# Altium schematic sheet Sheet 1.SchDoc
size 431 x 279 mm
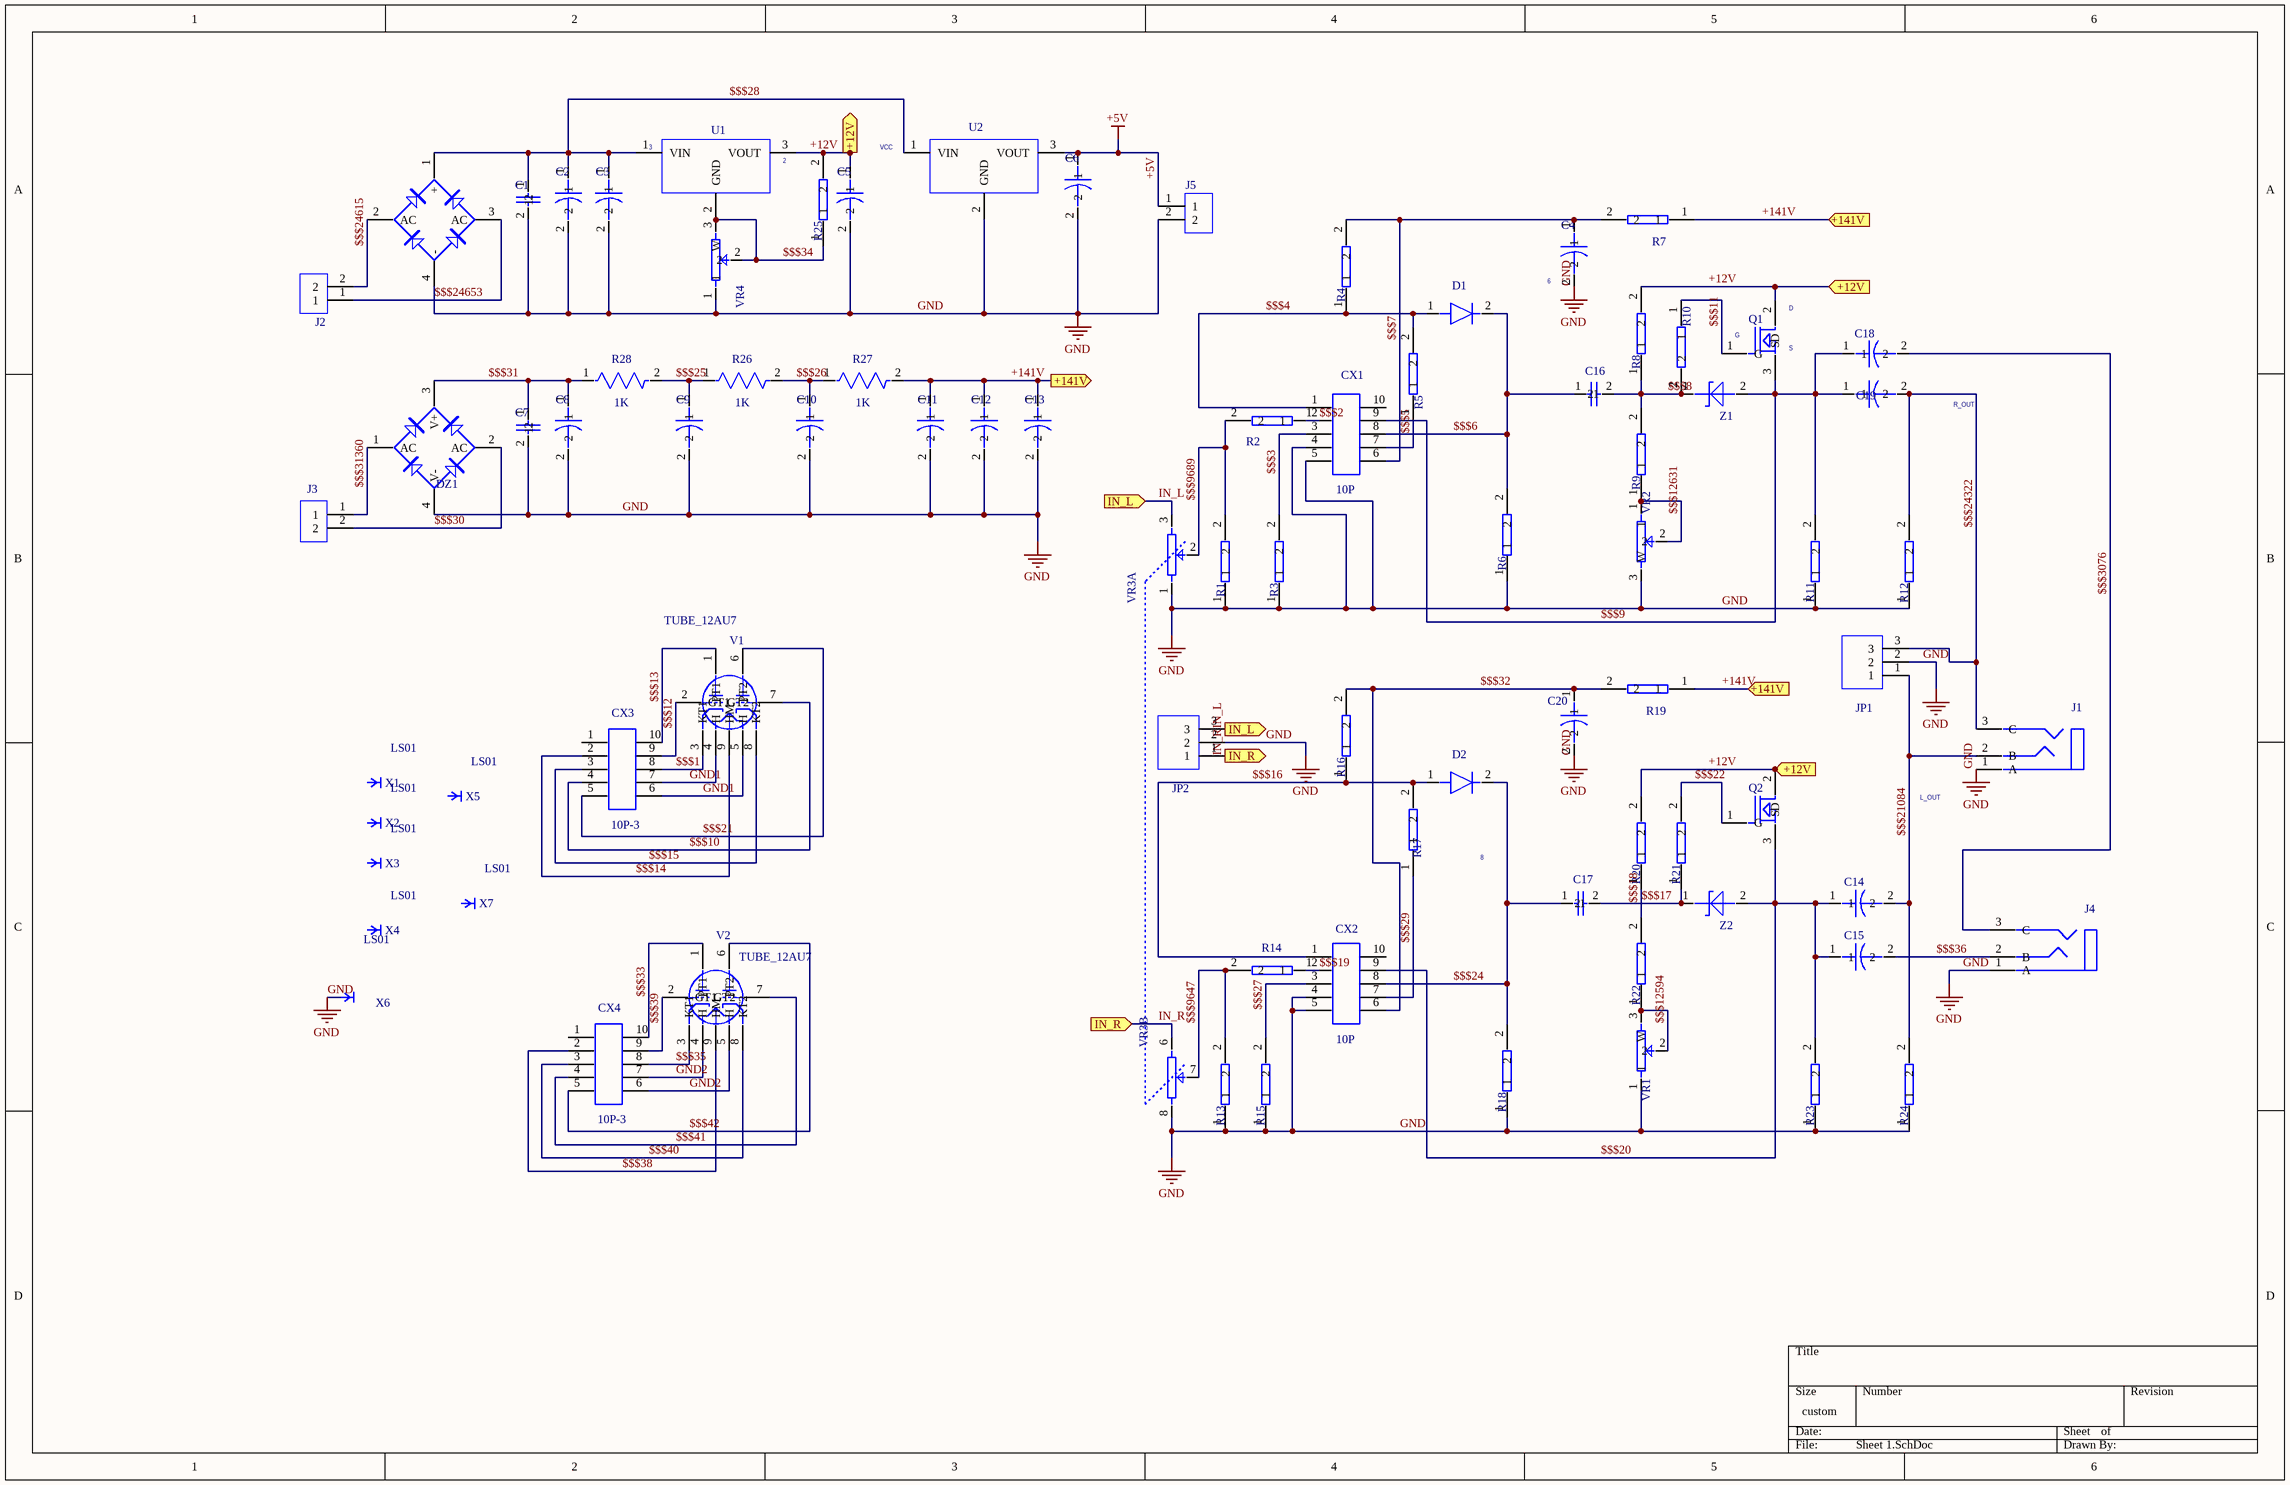
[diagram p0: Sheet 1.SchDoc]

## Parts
C1  CAP  (value not drawn)
C2  CAPACITOR_POL  (value not drawn)
C3  CAPACITOR_POL  (value not drawn)
C4  CAPACITOR_POL  (value not drawn)
C5  CAPACITOR_POL  (value not drawn)
C6  CAPACITOR_POL  (value not drawn)
C7  CAP  (value not drawn)
C8  CAPACITOR_POL  (value not drawn)
C9  CAPACITOR_POL  (value not drawn)
C10  CAPACITOR_POL  (value not drawn)
C11  CAPACITOR_POL  (value not drawn)
C12  CAPACITOR_POL  (value not drawn)
C13  CAPACITOR_POL  (value not drawn)
C14  CAP-5  (value not drawn)
C15  CAP-5  (value not drawn)
C16  CAP  (value not drawn)
C17  CAP  (value not drawn)
C18  CAP-5  (value not drawn)
C19  CAP-5  (value not drawn)
C20  CAPACITOR_POL  (value not drawn)
CX1  10P
CX2  10P
CX3  10P-3
CX4  10P-3
D1  FR107  (value not drawn)
D2  FR107  (value not drawn)
D3  KBL-5.0  (value not drawn)
DZ1  BRIDGE2  (value not drawn)
J1  M6.5  (value not drawn)
J2  CON2  (value not drawn)
J3  CON2  (value not drawn)
J4  M6.5  (value not drawn)
J5  CON2  (value not drawn)
JP1  HEADER_3  (value not drawn)
JP2  HEADER_3  (value not drawn)
Q1  IRF640  (value not drawn)
Q2  IRF640  (value not drawn)
R1  RES2  (value not drawn)
R2  RES2  (value not drawn)
R3  RES2  (value not drawn)
R4  RES2  (value not drawn)
R5  RES2  (value not drawn)
R6  RES2  (value not drawn)
R7  RES2  (value not drawn)
R8  RES2  (value not drawn)
R9  RES2  (value not drawn)
R10  RES2  (value not drawn)
R11  RES2  (value not drawn)
R12  RES2  (value not drawn)
R13  RES2  (value not drawn)
R14  RES2  (value not drawn)
R15  RES2  (value not drawn)
R16  RES2  (value not drawn)
R17  RES2  (value not drawn)
R18  RES2  (value not drawn)
R19  RES2  (value not drawn)
R20  RES2  (value not drawn)
R21  RES2  (value not drawn)
R22  RES2  (value not drawn)
R23  RES2  (value not drawn)
R24  RES2  (value not drawn)
R25  RES2  (value not drawn)
R26  value 1K  (hidden comment: RES-1W)
R27  value 1K  (hidden comment: RES-1W)
R28  value 1K  (hidden comment: RES-1W)
U1  VOLTREG  (value not drawn)
U2  VOLTREG  (value not drawn)
V1  TUBE_12AU7
V2  TUBE_12AU7
VR1  RP-3296  (value not drawn)
VR2  RP-3296  (value not drawn)
VR3  VR-27  (value not drawn)  (parts A,B of 2)
VR4  RP-3296  (value not drawn)
X1  LS01
X2  LS01
X3  LS01
X4  LS01
X5  LS01
X6  LS01
X7  LS01
Z1  ZENER2  (value not drawn)
Z2  ZENER2  (value not drawn)

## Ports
+12V, +141V, IN_L, IN_R

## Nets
$$$24653: C1.2 C2.2 C3.2 C4.2 C5.2 C6.2 C7.2 C8.2 C9.2 C10.2 C11.2 C12.2 C13.2 C20.2 CX1.4 CX1.5 CX2.4 CX2.5 D3.3(AC) D3.4(-) DZ1.4(V-) J1.1(A) J2.1 J4.1(A) J5.2 JP1.2 JP2.2 R1.1 R3.1 R6.1 R11.1 R12.1 R13.1 R15.1 R18.1 R23.1 R24.1 U2.2(GND) VR1.1 VR2.3(W) VR3.1 VR3.8 VR4.1  [also labelled GND]
+5V: C6.1 J5.1 U2.3(VOUT)
$$$1: CX3.8 V1.3(KT1)
$$$2: CX1.2 R2.1
$$$3: CX1.3 R3.2
$$$4: CX1.1 D1.1 R4.1 R5.2
$$$5: C16.1 C18.1 C19.1 CX1.7 CX1.8 CX1.9 D1.2 Q1.3(S) R5.1 R6.2 R11.2 Z1.2  [also labelled $$$6, $$$9]
$$$7: C4.1 CX1.6 R4.2 R7.2
$$$8: C16.2 R8.1 R9.2 R10.2 Z1.1
$$$10: CX3.4 V1.7(GT2)
$$$11: Q1.1(G) R10.1
$$$12: CX3.9 V1.2(GT1)
$$$13: CX3.10 V1.1(PT1)
$$$14: CX3.2 V1.9(HM)
$$$15: CX3.3 V1.8(KT2)
$$$16: CX2.1 D2.1 R16.1 R17.2
$$$17: C17.2 R20.1 R21.1 R22.2 Z2.1  [also labelled $$$18]
$$$19: CX2.2 R14.1
$$$20: C14.1 C15.1 CX2.9 Q2.3(S) R23.2 Z2.2
$$$21: CX3.5 V1.6(PT2)
$$$22: Q2.1(G) R21.2
$$$24: C17.1 CX2.8 D2.2 R18.2
$$$25: C9.1 R26.1 R28.2
$$$26: C10.1 R26.2 R27.1
$$$27: CX2.3 R15.2
$$$28: C1.1 C2.1 C3.1 D3.1(+) U1.1(VIN) U2.1(VIN)
$$$29: CX2.7 R17.1
$$$30: DZ1.2(AC) J3.2
$$$31: C7.1 C8.1 DZ1.3(V+) R28.1
$$$32: C20.1 CX2.6 R16.2 R19.2
$$$33: CX4.10 V2.1(PT1)
$$$34: R25.1 U1.2(GND) VR4.2 VR4.3(W)
$$$35: CX4.8 V2.3(KT1)
$$$36: C15.2 J4.2(B)
$$$38: CX4.2 V2.9(HM)
$$$39: CX4.9 V2.2(GT1)
$$$40: CX4.3 V2.8(KT2)
$$$41: CX4.4 V2.7(GT2)
$$$42: CX4.5 V2.6(PT2)
$$$3076: C18.2 J4.3(C)
$$$9647: R13.2 R14.2 VR3.7
$$$9689: R1.2 R2.2 VR3.2
$$$12594: R22.1 VR1.2 VR1.3(W)
$$$12631: R9.1 VR2.1 VR2.2
$$$21084: C14.2 J1.2(B) JP1.1 R24.2
$$$24322: C19.2 J1.3(C) JP1.3 R12.2
$$$24615: D3.2(AC) J2.2
$$$31360: DZ1.1(AC) J3.1
+12V: C5.1 Q1.2(D) Q2.2(D) R8.2 R20.2 R25.2 U1.3(VOUT) ; port +12V
+141V: C11.1 C12.1 C13.1 R7.1 R19.1 R27.2 ; port +141V
GND1: CX3.6 CX3.7 V1.4(H) V1.5(H)
GND2: CX4.6 CX4.7 V2.4(H) V2.5(H)
IN_L: JP2.3 VR3.3 ; port IN_L
IN_R: JP2.1 VR3.6 ; port IN_R

Not connected (* = marked no-connect by the designer): CX1 10; CX2 10; CX3 1; CX4 1

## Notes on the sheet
- (near U1) 3
- (near U1) 2
- VCC
- (near C4) 6
- (near Q1) G
- (near Q1) D
- (near Q1) S
- R_OUT
- L_OUT
- 8

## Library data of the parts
C1 C7 = CAP: Capacitor; Value: ???; PCB DECAL: CAP-300MIL
C2-C6 C8-C13 C20 = CAPACITOR_POL: Capacitor; VALUE: 22UF/250V; PCB DECAL: CAP-7.6
C14 C15 C18 C19 = CAP-5: Capacitor; VALUE: 470/25v
C16 C17 = CAP: Capacitor; Value: 0.22UF/63V; PCB DECAL: CAP-300MIL
D1 D2 = FR107: SURFACE MOUNT DIODE, MELF (SOD-80); Manufacturer #1: IPC SM-782; PCB DECAL: FR207
D3 = KBL-5.0: Diode Bridge
DZ1 = BRIDGE2: Diode Bridge; VALUE: D1; PCB DECAL: DB107
J1 J4 = M6.5: VALUE: PH1
J2 J3 J5 = CON2: Connector; VALUE: AC12V; PCB DECAL: CX
JP1 JP2 = HEADER_3: PCB DECAL: CX3P
Q1 Q2 = IRF640: VALUE: IRF610; PCB DECAL: TO220-4
R1-R25 = RES2: PCB DECAL: R1/2W
R26-R28 = RES-1W: RES  BODY:250  CENTERS:800; Sim.Analog.Order: Model$; Sim.Analog.Prefix: R; PCB DECAL: R1W
U1 U2 = VOLTREG: VALUE: lm317; PCB DECAL: TO220-5
V1 V2 = TUBE_12AU7: Medium Mu Dual Triode; Part_Field_Name_1: Published; Part_Field_Name_10: Part Field 10; Part_Field_Name_11: Part Field 11; VALUE: TUBE 12AU7; PCB DECAL: TUBE9M
VR1 VR2 VR4 = RP-3296: Potentiometer; VALUE: 100K; PCB DECAL: RP
Z1 Z2 = ZENER2: Zener Diode; VALUE: 5.2V; PCB DECAL: ZD01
